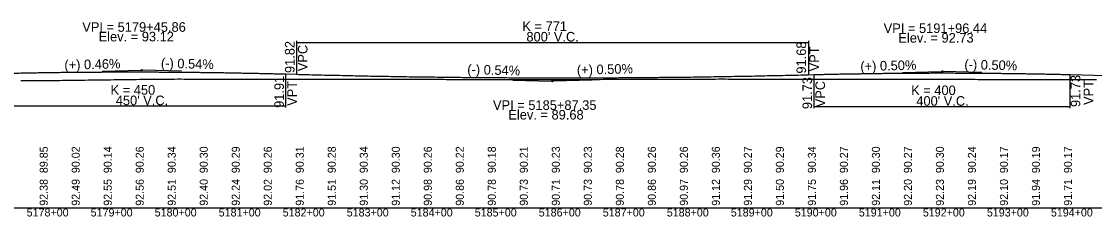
# Model space of a CAD drawing. Extents: x 2121671 to 2169879, y 557274 to 599957.
# Drawn here: x 2147326 to 2149002, y 576173 to 576479 of the extents above; entities that cross this region are included whole.
import ezdxf

# ---------------------------------------------------------------- set-up
doc = ezdxf.new("R2010")
doc.units = 0
for name, color, linetype in [('RD_DDB_GradeTX', 7, 'Continuous'), ('RD_DDB_Profile_EX', 7, 'Continuous'), ('RD_DDB_Profile_Lbl', 7, 'Continuous'), ('RD_DDB_Profile_PR', 7, 'Continuous'), ('RD_DDB_StaTX', 7, 'Continuous'), ('RD_DDB_StripGrade', 7, 'Continuous'), ('RD_DDB_VCLbl', 7, 'Continuous'), ('RD_GPK_Profile_Cell', 7, 'Continuous')]:
    doc.layers.add(name, color=color, linetype=linetype)

msp = doc.modelspace()

# ---------------------------------------------------------------- linework, layer by layer
at = {"layer": 'RD_DDB_GradeTX'}
for p, q in [((2147451.8, 576401), (2147512.8, 576402.4)), ((2147575.8, 576400.8), (2147514.8, 576402.4)), ((2148702.4, 576398.9), (2148763.4, 576400.5)), ((2148826.3, 576398.9), (2148765.4, 576400.5)), ((2148093.3, 576386.9), (2148154.3, 576385.2)), ((2148217.3, 576386.8), (2148156.3, 576385.2))]:
    msp.add_line(p, q, dxfattribs=at)
for centre in [(2147513.8, 576402.4), (2148764.4, 576400.5), (2148155.3, 576385.2)]:
    msp.add_circle(centre, 1, dxfattribs=at)
at = {"layer": 'RD_DDB_Profile_EX'}
for points in [[(2147325.1, 576386.4), (2147330.1, 576386.3), (2147335.1, 576386.3), (2147340.1, 576386.3), (2147345.1, 576386.2), (2147350.1, 576386.2), (2147355.1, 576386.2), (2147360.1, 576386.1), (2147365.1, 576386.1), (2147370.1, 576386.1), (2147375.1, 576386.2), (2147380.1, 576386.3), (2147385.1, 576386.4), (2147390.1, 576386.5), (2147395.1, 576386.5), (2147400.1, 576386.6), (2147405.1, 576386.7), (2147410.1, 576386.8), (2147415.1, 576386.9), (2147420.1, 576387), (2147425.1, 576387), (2147430.1, 576387.1), (2147435.1, 576387.1), (2147440.1, 576387.2), (2147445.1, 576387.2), (2147450.1, 576387.3), (2147455.1, 576387.3), (2147460.1, 576387.4), (2147465.1, 576387.5), (2147470.1, 576387.6), (2147475.1, 576387.6), (2147480.1, 576387.7), (2147485.1, 576387.8), (2147490.1, 576387.8), (2147495.1, 576387.9), (2147500.1, 576388), (2147505.1, 576388), (2147510.1, 576388.1), (2147515.1, 576388.1), (2147520.1, 576388.2), (2147525.1, 576388.2), (2147530.1, 576388.3), (2147535.1, 576388.3), (2147540.1, 576388.4), (2147545.1, 576388.4), (2147550.1, 576388.4), (2147555.1, 576388.5), (2147560.1, 576388.5), (2147565.1, 576388.5), (2147570.1, 576388.6), (2147575.1, 576388.6), (2147580.1, 576388.5), (2147585.1, 576388.5), (2147590.1, 576388.5), (2147595.1, 576388.5), (2147600.1, 576388.4), (2147605.1, 576388.4), (2147610.1, 576388.4), (2147615.1, 576388.3), (2147620.1, 576388.3), (2147625.1, 576388.3), (2147630.1, 576388.3), (2147635.1, 576388.3), (2147640.1, 576388.3), (2147645.1, 576388.3), (2147650.1, 576388.3), (2147655.1, 576388.3), (2147660.1, 576388.3), (2147665.1, 576388.3), (2147670.1, 576388.3), (2147675.1, 576388.3), (2147680.1, 576388.2), (2147685.1, 576388.2), (2147690.1, 576388.2), (2147695.1, 576388.2), (2147700.1, 576388.2), (2147705.1, 576388.2), (2147710.1, 576388.2), (2147715.1, 576388.1), (2147720.1, 576388.1), (2147725.1, 576388.1)], [(2147725.1, 576388.1), (2147730.1, 576388.1), (2147735.1, 576388.1), (2147740.1, 576388.1), (2147745.1, 576388.2), (2147750.1, 576388.2), (2147755.1, 576388.3), (2147760.1, 576388.3), (2147765.1, 576388.4), (2147770.1, 576388.4), (2147775.1, 576388.4), (2147780.1, 576388.4), (2147785.1, 576388.4), (2147790.1, 576388.3), (2147795.1, 576388.3), (2147800.1, 576388.3), (2147805.1, 576388.2), (2147810.1, 576388.2), (2147815.1, 576388.2), (2147820.1, 576388.2), (2147825.1, 576388.3), (2147830.1, 576388.3), (2147835.1, 576388.3), (2147840.1, 576388.4), (2147845.1, 576388.4), (2147850.1, 576388.5), (2147855.1, 576388.5), (2147860.1, 576388.5), (2147865.1, 576388.5), (2147870.1, 576388.5), (2147875.1, 576388.5), (2147880.1, 576388.5), (2147885.1, 576388.5), (2147890.1, 576388.5), (2147895.1, 576388.5), (2147900.1, 576388.5), (2147905.1, 576388.4), (2147910.1, 576388.4), (2147915.1, 576388.4), (2147920.1, 576388.3), (2147925.1, 576388.3), (2147930.1, 576388.3), (2147935.1, 576388.2), (2147940.1, 576388.2), (2147945.1, 576388.2), (2147950.1, 576388.2), (2147955.1, 576388.1), (2147960.1, 576388.1), (2147965.1, 576388.1), (2147970.1, 576388.1), (2147975.1, 576388.1), (2147980.1, 576388.1), (2147985.1, 576388.1), (2147990.1, 576388), (2147995.1, 576388), (2148000.1, 576388), (2148005.1, 576388), (2148010.1, 576388), (2148015.1, 576388), (2148020.1, 576387.9), (2148025.1, 576387.9), (2148030.1, 576387.9), (2148035.1, 576387.9), (2148040.1, 576387.8), (2148045.1, 576387.8), (2148050.1, 576387.8), (2148055.1, 576387.7), (2148060.1, 576387.7), (2148065.1, 576387.7), (2148070.1, 576387.7), (2148075.1, 576387.8), (2148080.1, 576387.8), (2148085.1, 576387.8), (2148090.1, 576387.8), (2148095.1, 576387.8), (2148100.1, 576387.8), (2148105.1, 576387.9), (2148110.1, 576387.9), (2148115.1, 576387.9), (2148120.1, 576387.9), (2148125.1, 576387.9), (2148130.1, 576387.9), (2148135.1, 576387.9), (2148140.1, 576387.9), (2148145.1, 576388), (2148150.1, 576388), (2148155.1, 576388), (2148160.1, 576388), (2148165.1, 576388), (2148170.1, 576388), (2148175.1, 576388), (2148180.1, 576388), (2148185.1, 576388), (2148190.1, 576388), (2148195.1, 576388), (2148200.1, 576388), (2148205.1, 576388), (2148210.1, 576388), (2148215.1, 576388), (2148220.1, 576388), (2148225.1, 576388)], [(2148225.1, 576388), (2148230.1, 576388), (2148235.1, 576388.1), (2148240.1, 576388.1), (2148245.1, 576388.1), (2148250.1, 576388.2), (2148255.1, 576388.2), (2148260.1, 576388.2), (2148265.1, 576388.2), (2148270.1, 576388.2), (2148275.1, 576388.2), (2148280.1, 576388.2), (2148285.1, 576388.2), (2148290.1, 576388.2), (2148295.1, 576388.2), (2148300.1, 576388.1), (2148305.1, 576388.1), (2148310.1, 576388.1), (2148315.1, 576388.1), (2148320.1, 576388.1), (2148325.1, 576388.1), (2148330.1, 576388.1), (2148335.1, 576388.1), (2148340.1, 576388.1), (2148345.1, 576388.1), (2148350.1, 576388.1), (2148355.1, 576388.1), (2148360.1, 576388.1), (2148365.1, 576388.1), (2148370.1, 576388.1), (2148375.1, 576388.1), (2148380.1, 576388.1), (2148385.1, 576388.2), (2148390.1, 576388.3), (2148395.1, 576388.3), (2148400.1, 576388.4), (2148405.1, 576388.4), (2148410.1, 576388.5), (2148415.1, 576388.6), (2148420.1, 576388.6), (2148425.1, 576388.6), (2148430.1, 576388.5), (2148435.1, 576388.5), (2148440.1, 576388.4), (2148445.1, 576388.3), (2148450.1, 576388.3), (2148455.1, 576388.2), (2148460.1, 576388.1), (2148465.1, 576388.2), (2148470.1, 576388.2), (2148475.1, 576388.2), (2148480.1, 576388.2), (2148485.1, 576388.2), (2148490.1, 576388.3), (2148495.1, 576388.3), (2148500.1, 576388.3), (2148505.1, 576388.3), (2148510.1, 576388.3), (2148515.1, 576388.3), (2148520.1, 576388.3), (2148525.1, 576388.3), (2148530.1, 576388.3), (2148535.1, 576388.3), (2148540.1, 576388.3), (2148545.1, 576388.4), (2148550.1, 576388.4), (2148555.1, 576388.4), (2148560.1, 576388.5), (2148565.1, 576388.5), (2148570.1, 576388.5), (2148575.1, 576388.5), (2148580.1, 576388.4), (2148585.1, 576388.4), (2148590.1, 576388.3), (2148595.1, 576388.3), (2148600.1, 576388.3), (2148605.1, 576388.2), (2148610.1, 576388.2), (2148615.1, 576388.2), (2148620.1, 576388.2), (2148625.1, 576388.2), (2148630.1, 576388.2), (2148635.1, 576388.2), (2148640.1, 576388.2), (2148645.1, 576388.3), (2148650.1, 576388.3), (2148655.1, 576388.3), (2148660.1, 576388.3), (2148665.1, 576388.3), (2148670.1, 576388.3), (2148675.1, 576388.3), (2148680.1, 576388.4), (2148685.1, 576388.4), (2148690.1, 576388.4), (2148695.1, 576388.3), (2148700.1, 576388.3), (2148705.1, 576388.3), (2148710.1, 576388.2), (2148715.1, 576388.2), (2148720.1, 576388.2), (2148725.1, 576388.1)], [(2148725.1, 576388.1), (2148730.1, 576388.1), (2148735.1, 576388.2), (2148740.1, 576388.2), (2148745.1, 576388.2), (2148750.1, 576388.2), (2148755.1, 576388.2), (2148760.1, 576388.3), (2148765.1, 576388.3), (2148770.1, 576388.3), (2148775.1, 576388.3), (2148780.1, 576388.3), (2148785.1, 576388.3), (2148790.1, 576388.3), (2148795.1, 576388.3), (2148800.1, 576388.2), (2148805.1, 576388.2), (2148810.1, 576388.1), (2148815.1, 576388.1), (2148820.1, 576388), (2148825.1, 576387.9), (2148830.1, 576387.9), (2148835.1, 576387.8), (2148840.1, 576387.8), (2148845.1, 576387.7), (2148850.1, 576387.7), (2148855.1, 576387.7), (2148860.1, 576387.7), (2148865.1, 576387.7), (2148870.1, 576387.7), (2148875.1, 576387.8), (2148880.1, 576387.9), (2148885.1, 576387.9), (2148890.1, 576387.9), (2148895.1, 576387.9), (2148900.1, 576387.8), (2148905.1, 576387.8), (2148910.1, 576387.8), (2148915.1, 576387.8), (2148920.1, 576387.8), (2148925.1, 576387.8), (2148930.1, 576387.8), (2148935.1, 576387.7), (2148940.1, 576387.7), (2148945.1, 576387.7), (2148950.1, 576387.7), (2148955.1, 576387.7), (2148960.1, 576387.7), (2148965.1, 576387.7), (2148970.1, 576387.7), (2148975.1, 576387.7), (2148980.1, 576387.7), (2148985.1, 576387.7), (2148990.1, 576387.7), (2148995.1, 576387.7), (2149000.1, 576387.7), (2149005.1, 576387.7)]]:
    msp.add_lwpolyline(points, dxfattribs=at)
at = {"layer": 'RD_DDB_Profile_PR'}
for p, q in [((2147738.8, 576396.4), (2147755.3, 576395.9)), ((2148555.3, 576395.2), (2148564.4, 576395.5)), ((2148964.4, 576395.5), (2149161.1, 576390.6))]:
    msp.add_line(p, q, dxfattribs=at)
for points in [[(2147288.8, 576397.2), (2147297.8, 576397.4), (2147306.8, 576397.6), (2147315.8, 576397.8), (2147324.8, 576398), (2147333.8, 576398.2), (2147342.8, 576398.3), (2147351.8, 576398.5), (2147360.8, 576398.6), (2147369.8, 576398.7), (2147378.8, 576398.9), (2147387.8, 576399), (2147396.8, 576399.1), (2147405.8, 576399.2), (2147414.8, 576399.3), (2147423.8, 576399.3), (2147432.8, 576399.4), (2147441.8, 576399.5), (2147450.8, 576399.5), (2147459.8, 576399.6), (2147468.8, 576399.6), (2147477.8, 576399.6), (2147486.8, 576399.6), (2147495.8, 576399.6), (2147504.8, 576399.6), (2147513.8, 576399.6), (2147522.8, 576399.6), (2147531.8, 576399.6), (2147540.8, 576399.5), (2147549.8, 576399.5), (2147558.8, 576399.4), (2147567.8, 576399.4), (2147576.8, 576399.3), (2147585.8, 576399.2), (2147594.8, 576399.1), (2147603.8, 576399), (2147612.8, 576398.9), (2147621.8, 576398.8), (2147630.8, 576398.6), (2147639.8, 576398.5), (2147648.8, 576398.4), (2147657.8, 576398.2), (2147666.8, 576398), (2147675.8, 576397.9), (2147684.8, 576397.7), (2147693.8, 576397.5), (2147702.8, 576397.3), (2147711.8, 576397.1), (2147720.8, 576396.9), (2147729.8, 576396.6), (2147738.8, 576396.4)], [(2147755.3, 576395.9), (2147771.3, 576395.5), (2147787.3, 576395.1), (2147803.3, 576394.7), (2147819.3, 576394.4), (2147835.3, 576394), (2147851.3, 576393.7), (2147867.3, 576393.3), (2147883.3, 576393), (2147899.3, 576392.8), (2147915.3, 576392.5), (2147931.3, 576392.2), (2147947.3, 576392), (2147963.3, 576391.8), (2147979.3, 576391.6), (2147995.3, 576391.4), (2148011.3, 576391.2), (2148027.3, 576391), (2148043.3, 576390.9), (2148059.3, 576390.8), (2148075.3, 576390.7), (2148091.3, 576390.6), (2148107.3, 576390.5), (2148123.3, 576390.5), (2148139.3, 576390.4), (2148155.3, 576390.4), (2148171.3, 576390.4), (2148187.3, 576390.4), (2148203.3, 576390.4), (2148219.3, 576390.5), (2148235.3, 576390.5), (2148251.3, 576390.6), (2148267.3, 576390.7), (2148283.3, 576390.8), (2148299.3, 576390.9), (2148315.3, 576391.1), (2148331.3, 576391.3), (2148347.3, 576391.4), (2148363.3, 576391.6), (2148379.3, 576391.8), (2148395.3, 576392.1), (2148411.3, 576392.3), (2148427.3, 576392.6), (2148443.3, 576392.8), (2148459.3, 576393.1), (2148475.3, 576393.4), (2148491.3, 576393.8), (2148507.3, 576394.1), (2148523.3, 576394.5), (2148539.3, 576394.8), (2148555.3, 576395.2)], [(2148564.4, 576395.5), (2148572.4, 576395.7), (2148580.4, 576395.9), (2148588.4, 576396), (2148596.4, 576396.2), (2148604.4, 576396.4), (2148612.4, 576396.5), (2148620.4, 576396.7), (2148628.4, 576396.8), (2148636.4, 576396.9), (2148644.4, 576397.1), (2148652.4, 576397.2), (2148660.4, 576397.3), (2148668.4, 576397.4), (2148676.4, 576397.5), (2148684.4, 576397.6), (2148692.4, 576397.6), (2148700.4, 576397.7), (2148708.4, 576397.8), (2148716.4, 576397.8), (2148724.4, 576397.9), (2148732.4, 576397.9), (2148740.4, 576397.9), (2148748.4, 576398), (2148756.4, 576398), (2148764.4, 576398), (2148772.4, 576398), (2148780.4, 576398), (2148788.4, 576397.9), (2148796.4, 576397.9), (2148804.4, 576397.9), (2148812.4, 576397.8), (2148820.4, 576397.8), (2148828.4, 576397.7), (2148836.4, 576397.7), (2148844.4, 576397.6), (2148852.4, 576397.5), (2148860.4, 576397.4), (2148868.4, 576397.3), (2148876.4, 576397.2), (2148884.4, 576397.1), (2148892.4, 576397), (2148900.4, 576396.8), (2148908.4, 576396.7), (2148916.4, 576396.5), (2148924.4, 576396.4), (2148932.4, 576396.2), (2148940.4, 576396), (2148948.4, 576395.9), (2148956.4, 576395.7), (2148964.4, 576395.5)]]:
    msp.add_spline(points, degree=3, dxfattribs=at)
at = {"layer": 'RD_DDB_VCLbl'}
for p, q in [((2147755.3, 576448.4), (2147755.3, 576395.9)), ((2147755.3, 576445.9), (2148555.3, 576445.9)), ((2148555.3, 576448.4), (2148555.3, 576395.2)), ((2147738.8, 576343.9), (2147738.8, 576396.4)), ((2148564.4, 576343), (2148564.4, 576395.5)), ((2148964.4, 576343), (2148964.4, 576395.5)), ((2147288.8, 576346.4), (2147738.8, 576346.4)), ((2148564.4, 576345.5), (2148964.4, 576345.5))]:
    msp.add_line(p, q, dxfattribs=at)
at = {"layer": 'RD_GPK_Profile_Cell'}
msp.add_line((2146667.9, 576186.8), (2151167.9, 576186.8), dxfattribs=at)

# ---------------------------------------------------------------- texts
at = {"layer": 'RD_DDB_GradeTX'}
for s, rotation, p in [('(+) 0.46%', 1.3258, (2147393.1, 576403.1)), ('(-) 0.54%', 358.4628, (2147543.6, 576406.1)), ('(-) 0.54%', 358.4628, (2148022.2, 576396.3)), ('(+) 0.50%', 1.4356, (2148193.7, 576395.2)), ('(+) 0.50%', 1.4356, (2148636.5, 576400.9)), ('(-) 0.50%', 358.5698, (2148798.7, 576404.1))]:
    msp.add_text(s, height=15, rotation=rotation, dxfattribs=at).set_placement(p)
at = {"layer": 'RD_DDB_Profile_Lbl'}
for s, p in [('VPI = 5179+45.86', (2147420.9, 576462.4)), ('Elev. = 93.12', (2147446.4, 576447.4)), ('VPI = 5191+96.44', (2148672.8, 576460.5)), ('Elev. = 92.73', (2148695.7, 576445.5)), ('VPI = 5185+87.35', (2148062.5, 576340.2)), ('Elev. = 89.68', (2148086.5, 576325.2))]:
    msp.add_text(s, height=15, dxfattribs=at).set_placement(p)
at = {"layer": 'RD_DDB_StaTX'}
for s, p in [('5178+00', (2147334, 576173.5)), ('5179+00', (2147434, 576173.5)), ('5180+00', (2147534, 576173.5)), ('5181+00', (2147634, 576173.5)), ('5182+00', (2147734, 576173.5)), ('5183+00', (2147834, 576173.5)), ('5184+00', (2147934, 576173.5)), ('5185+00', (2148034, 576173.5)), ('5186+00', (2148134, 576173.5)), ('5187+00', (2148234, 576173.5)), ('5188+00', (2148334, 576173.5)), ('5189+00', (2148434, 576173.5)), ('5190+00', (2148534, 576173.5)), ('5191+00', (2148634, 576173.5)), ('5192+00', (2148734, 576173.5)), ('5193+00', (2148834, 576173.5)), ('5194+00', (2148934, 576173.5))]:
    msp.add_text(s, height=12.5, dxfattribs=at).set_placement(p)
at = {"layer": 'RD_DDB_StripGrade'}
for s, height, p in [('91.82 ', 15, (2147752.5, 576397.9)), ('91.68 ', 15, (2148551.6, 576397)), ('VPC', 15, (2147772.7, 576400.8)), ('VPT', 15, (2148571.8, 576400.5)), ('91.91 ', 15, (2147735.9, 576343.4)), ('91.73 ', 15, (2148980, 576344.7)), ('VPT', 15, (2147756.1, 576346.5)), ('91.73 ', 15, (2148561, 576341.4)), ('VPC', 15, (2148581.2, 576344.3)), ('VPT', 15, (2149000.2, 576347.9)), ('89.85', 12.5, (2147366.9, 576241.3)), ('90.02', 12.5, (2147416.9, 576241.3)), ('90.14', 12.5, (2147466.9, 576241.3)), ('90.26', 12.5, (2147516.9, 576241.3)), ('90.34', 12.5, (2147566.9, 576241.3)), ('90.30', 12.5, (2147616.9, 576241.3)), ('90.29', 12.5, (2147666.9, 576241.3)), ('90.26', 12.5, (2147716.9, 576241.3)), ('90.31', 12.5, (2147766.9, 576241.3)), ('90.28', 12.5, (2147816.9, 576241.3)), ('90.34', 12.5, (2147866.9, 576241.3)), ('90.30', 12.5, (2147916.9, 576241.3)), ('90.26', 12.5, (2147966.9, 576241.3)), ('90.22', 12.5, (2148016.9, 576241.3)), ('90.18', 12.5, (2148066.9, 576241.3)), ('90.21', 12.5, (2148116.9, 576241.3)), ('90.23', 12.5, (2148166.9, 576241.3)), ('90.23', 12.5, (2148216.9, 576241.3)), ('90.28', 12.5, (2148266.9, 576241.3)), ('90.26', 12.5, (2148316.9, 576241.3)), ('90.26', 12.5, (2148366.9, 576241.3)), ('90.36', 12.5, (2148416.9, 576241.3)), ('90.27', 12.5, (2148466.9, 576241.3)), ('90.29', 12.5, (2148516.9, 576241.3)), ('90.34', 12.5, (2148566.9, 576241.3)), ('90.27', 12.5, (2148616.9, 576241.3)), ('90.30', 12.5, (2148666.9, 576241.3)), ('90.27', 12.5, (2148716.9, 576241.3)), ('90.30', 12.5, (2148766.9, 576241.3)), ('90.24', 12.5, (2148816.9, 576241.3)), ('90.17', 12.5, (2148866.9, 576241.3)), ('90.19', 12.5, (2148916.9, 576241.3)), ('90.17', 12.5, (2148966.9, 576241.3)), ('92.38', 12.5, (2147366.9, 576190.3)), ('92.49', 12.5, (2147416.9, 576190.3)), ('92.55', 12.5, (2147466.9, 576190.3)), ('92.56', 12.5, (2147516.9, 576190.3)), ('92.51', 12.5, (2147566.9, 576190.3)), ('92.40', 12.5, (2147616.9, 576190.3)), ('92.24', 12.5, (2147666.9, 576190.3)), ('92.02', 12.5, (2147716.9, 576190.3)), ('91.76', 12.5, (2147766.9, 576190.3)), ('91.51', 12.5, (2147816.9, 576190.3)), ('91.30', 12.5, (2147866.9, 576190.3)), ('91.12', 12.5, (2147916.9, 576190.3)), ('90.98', 12.5, (2147966.9, 576190.3)), ('90.86', 12.5, (2148016.9, 576190.3)), ('90.78', 12.5, (2148066.9, 576190.3)), ('90.73', 12.5, (2148116.9, 576190.3)), ('90.71', 12.5, (2148166.9, 576190.3)), ('90.73', 12.5, (2148216.9, 576190.3)), ('90.78', 12.5, (2148266.9, 576190.3)), ('90.86', 12.5, (2148316.9, 576190.3)), ('90.97', 12.5, (2148366.9, 576190.3)), ('91.12', 12.5, (2148416.9, 576190.3)), ('91.29', 12.5, (2148466.9, 576190.3)), ('91.50', 12.5, (2148516.9, 576190.3)), ('91.75', 12.5, (2148566.9, 576190.3)), ('91.96', 12.5, (2148616.9, 576190.3)), ('92.11', 12.5, (2148666.9, 576190.3)), ('92.20', 12.5, (2148716.9, 576190.3)), ('92.23', 12.5, (2148766.9, 576190.3)), ('92.19', 12.5, (2148816.9, 576190.3)), ('92.10', 12.5, (2148866.9, 576190.3)), ('91.94', 12.5, (2148916.9, 576190.3)), ('91.71', 12.5, (2148966.9, 576190.3))]:
    msp.add_text(s, height=height, rotation=90, dxfattribs=at).set_placement(p)
at = {"layer": 'RD_DDB_VCLbl'}
for s, p in [('K = 771', (2148108.4, 576463.6)), ("800' V.C.", (2148114.7, 576447.2)), ('K = 450', (2147465.1, 576364)), ('K = 400', (2148715.7, 576363.4)), ("450' V.C.", (2147473.2, 576347.6)), ("400' V.C.", (2148723.8, 576346.7))]:
    msp.add_text(s, height=15, dxfattribs=at).set_placement(p)

doc.saveas('drawing.dxf')
